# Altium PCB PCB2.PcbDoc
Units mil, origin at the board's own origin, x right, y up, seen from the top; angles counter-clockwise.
Board outline 1968.5 x 1968.5 mil, 4 copper layers (Top Layer, Internal Plane 1, Internal Plane 2, Bottom Layer), stack 18.2 mil thick; 11 components, 10 nets, 36 pads, 0 vias.
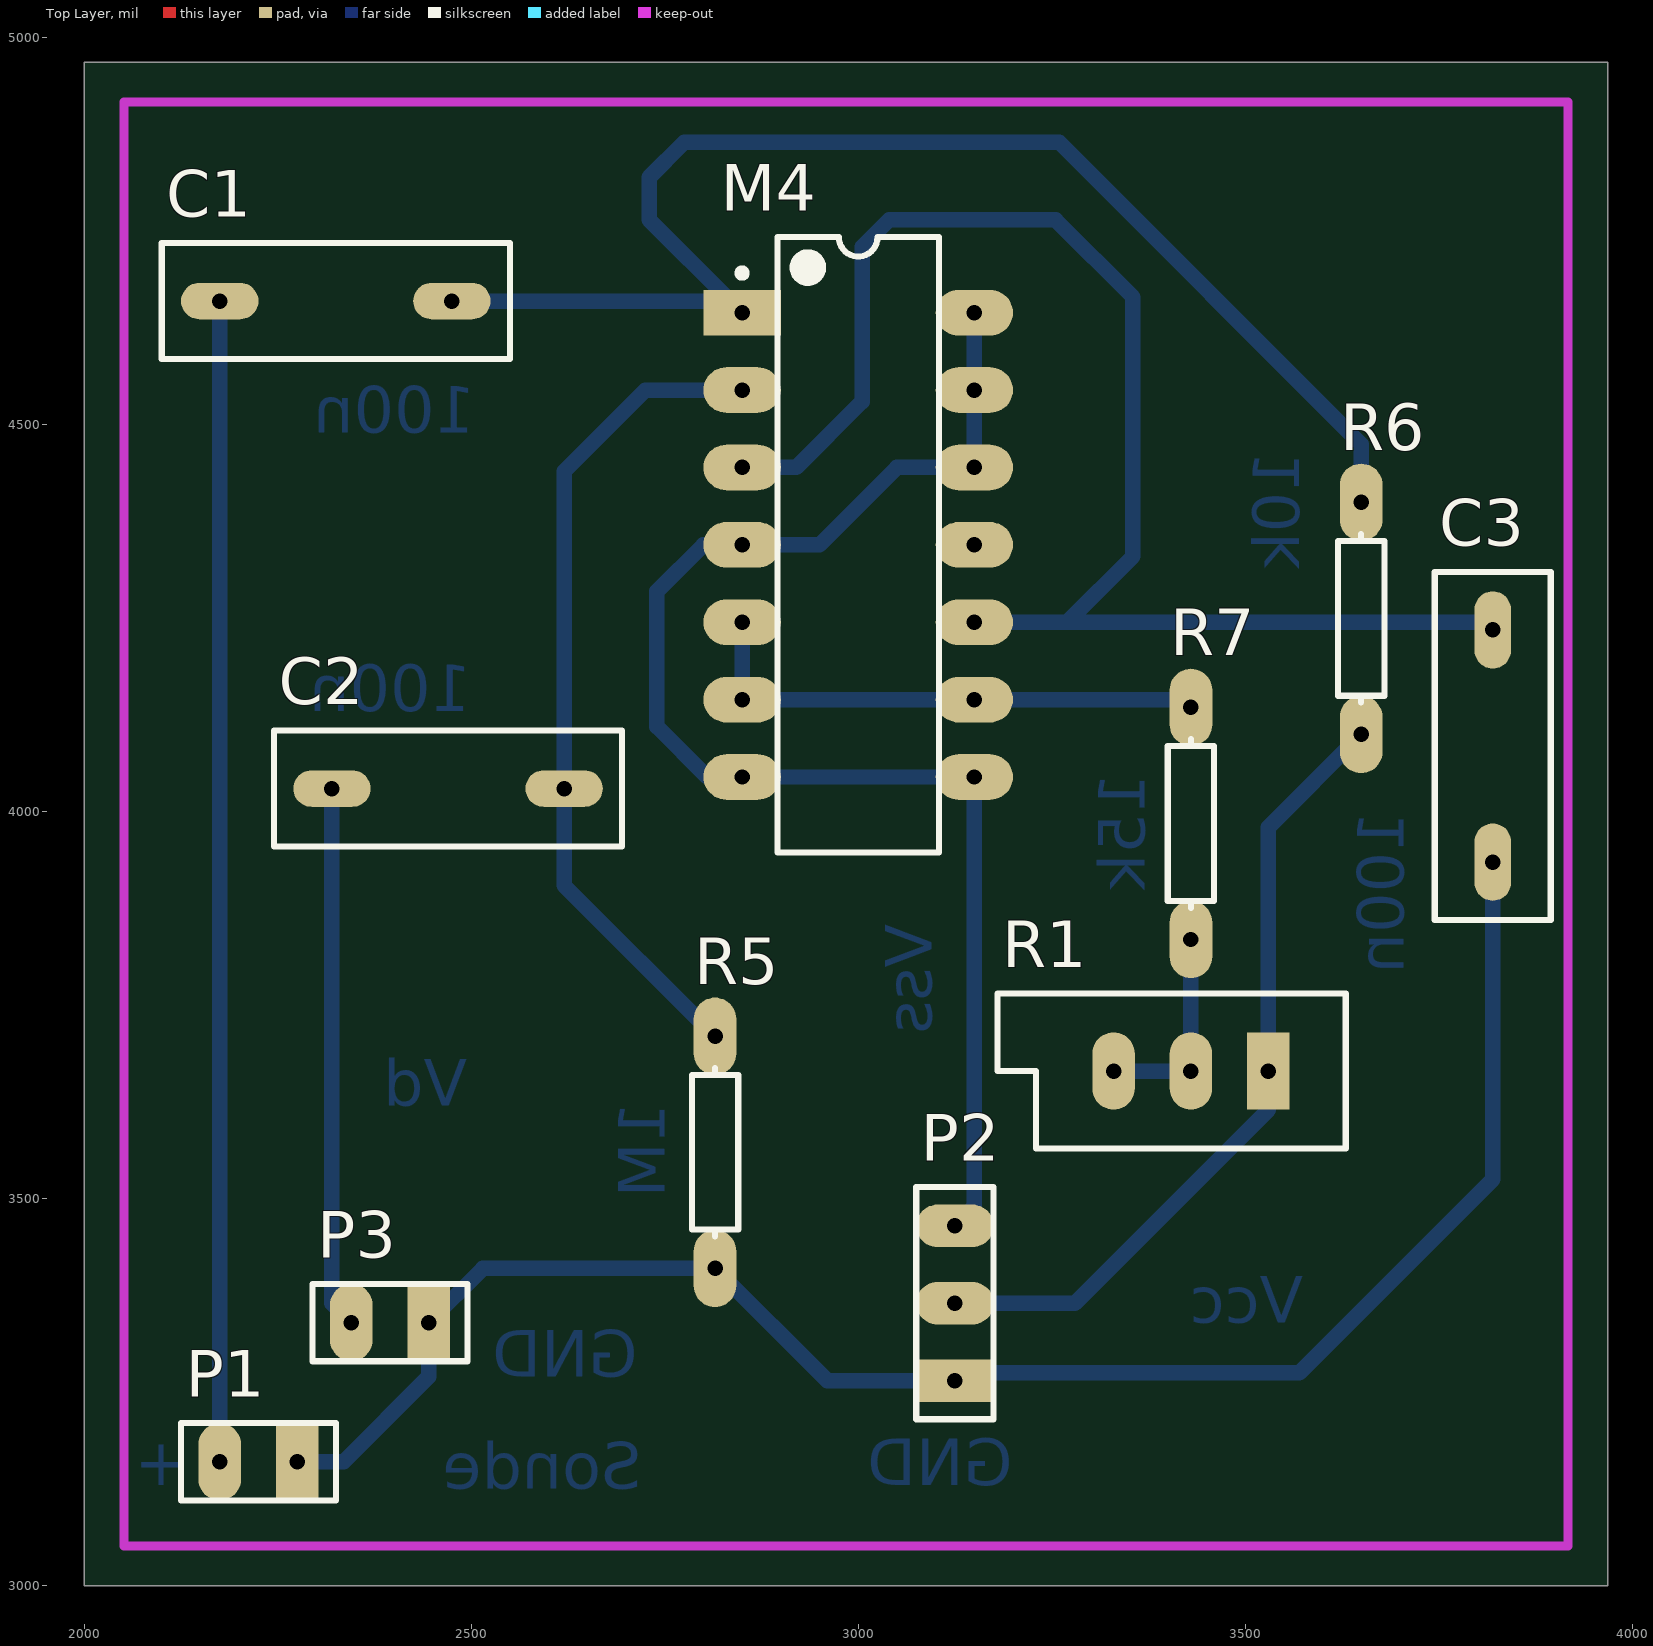
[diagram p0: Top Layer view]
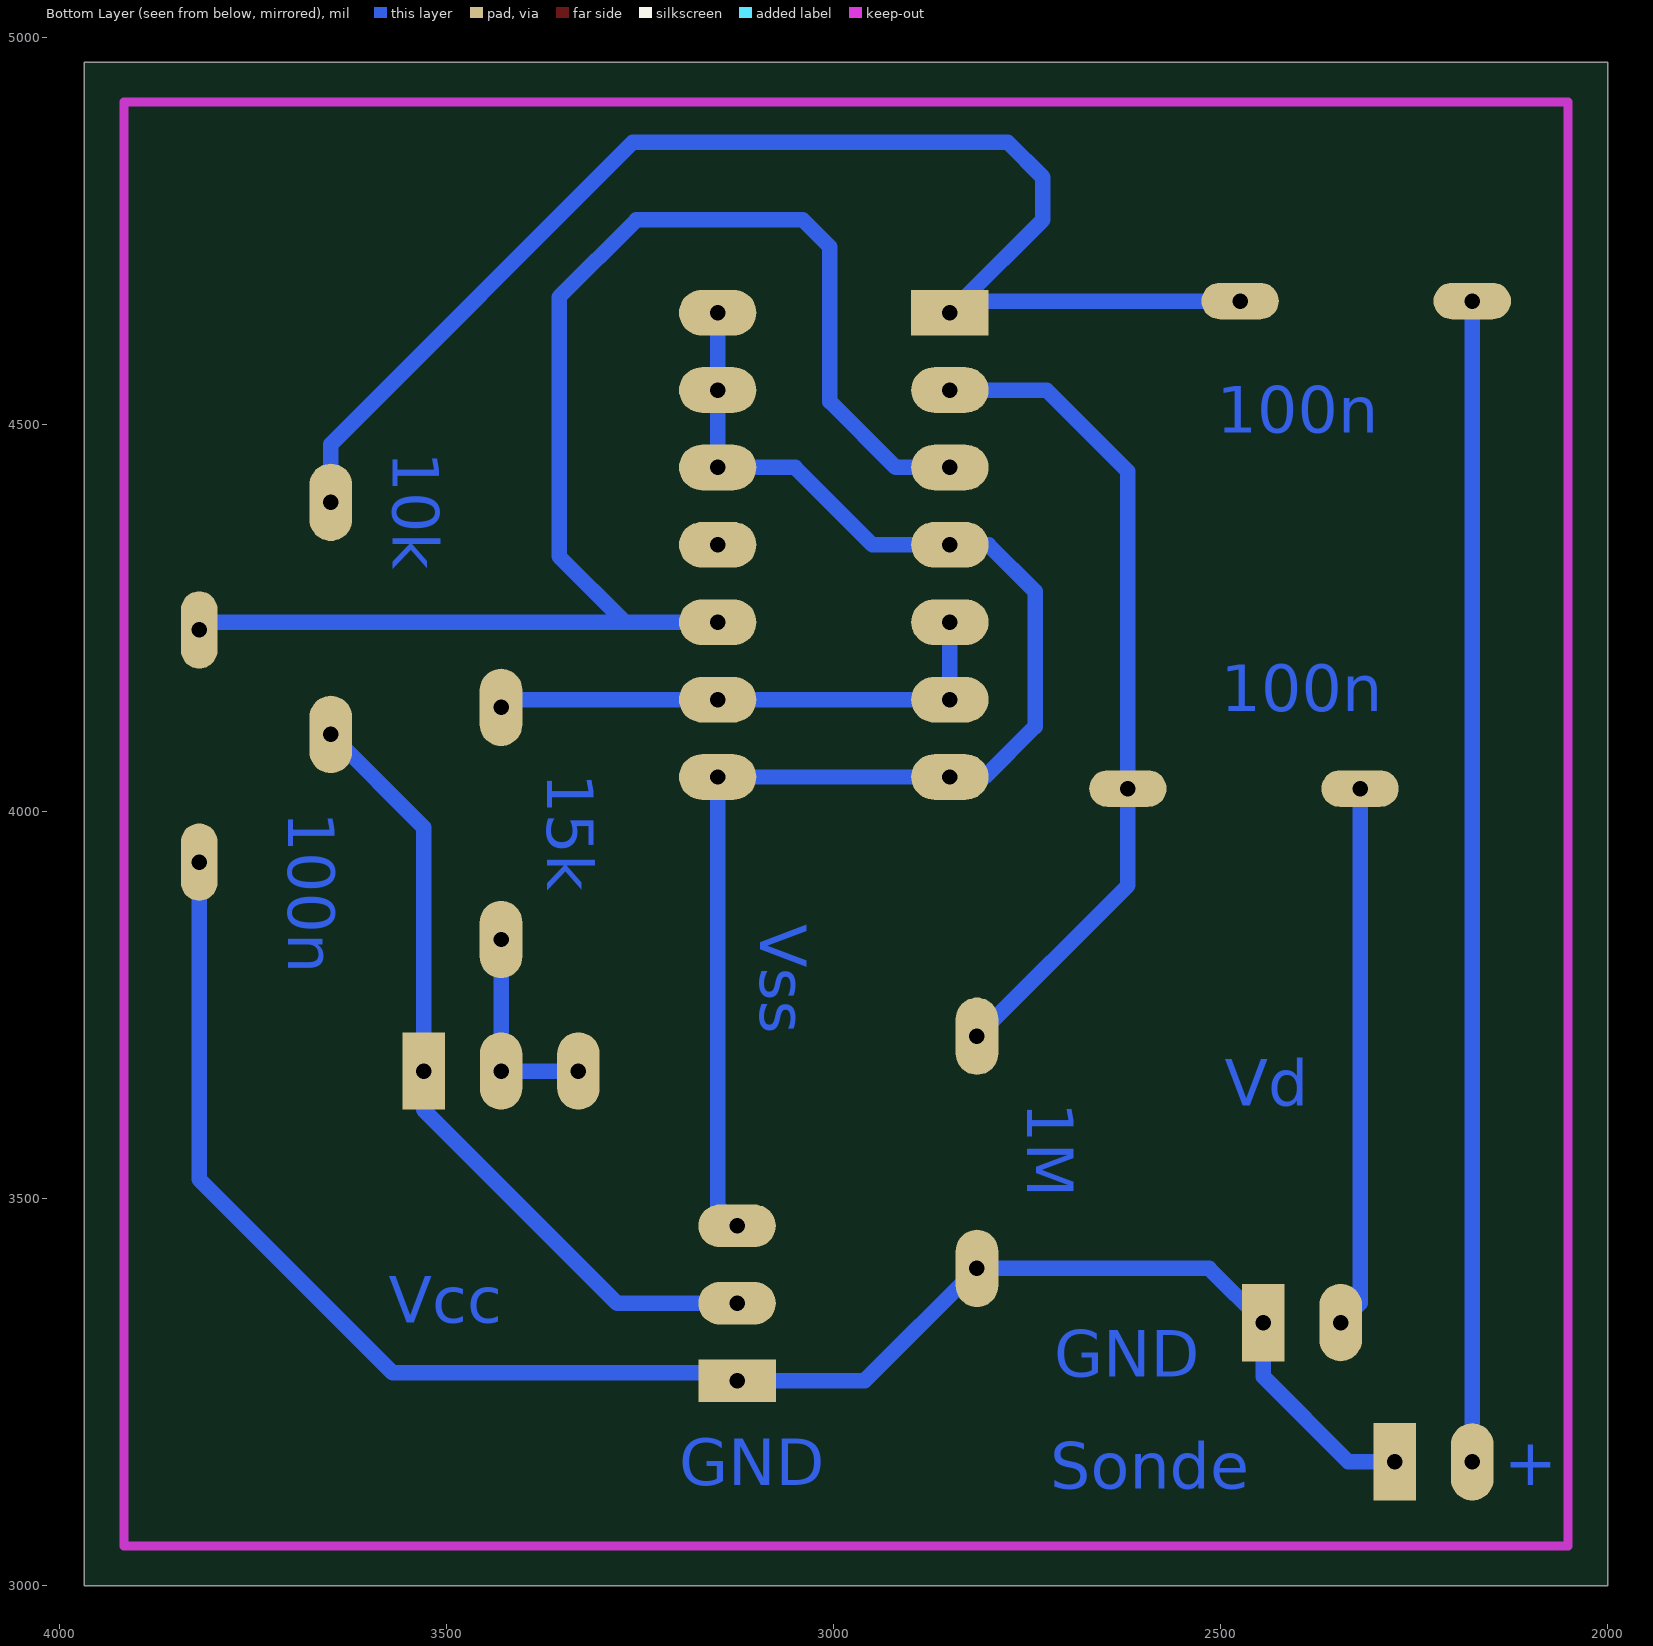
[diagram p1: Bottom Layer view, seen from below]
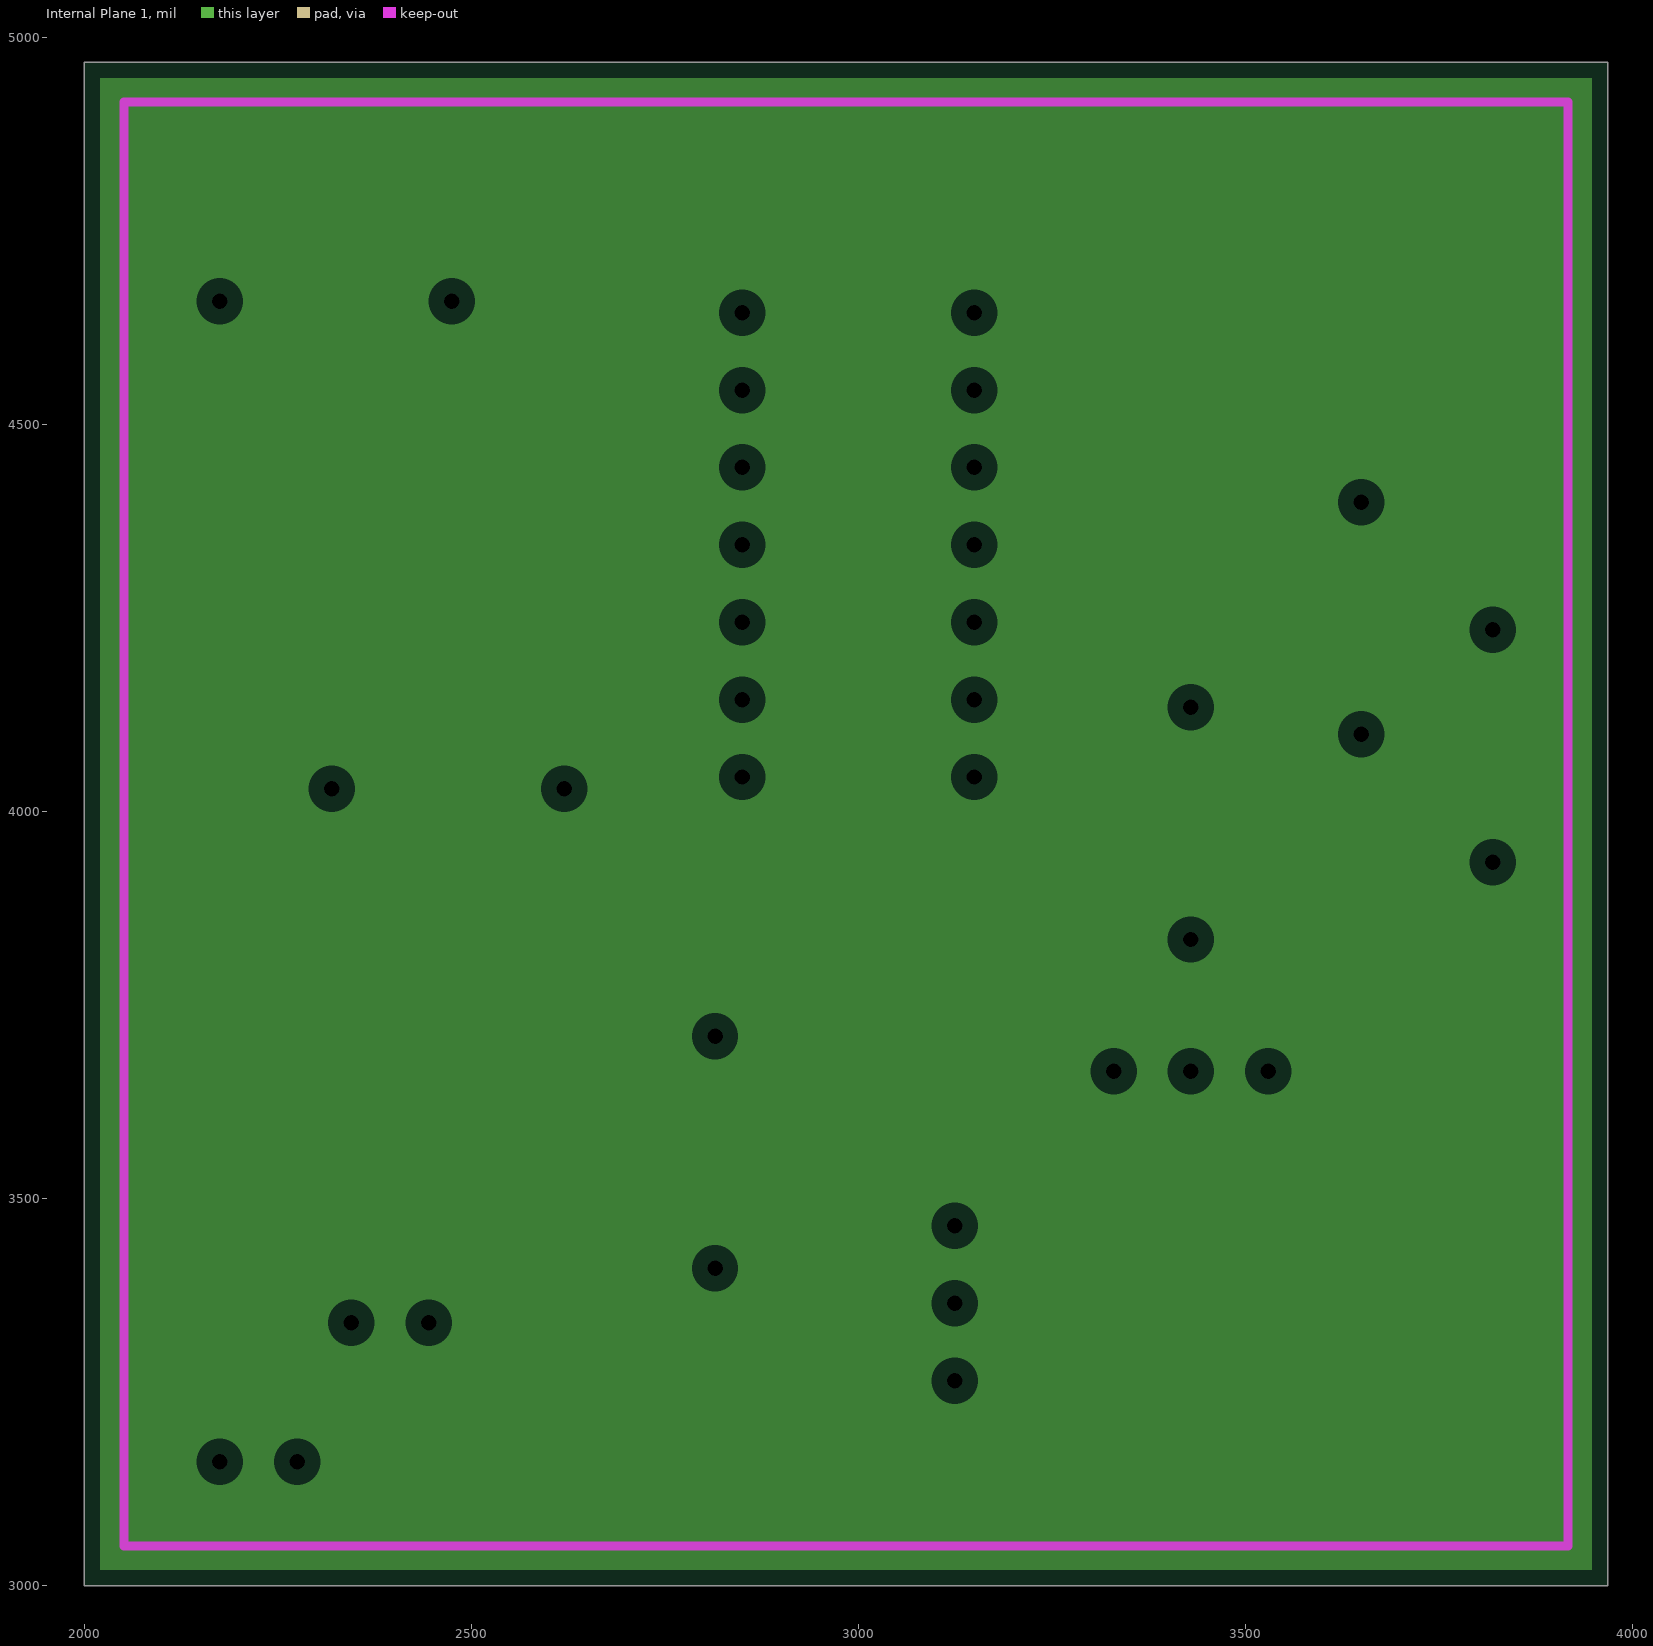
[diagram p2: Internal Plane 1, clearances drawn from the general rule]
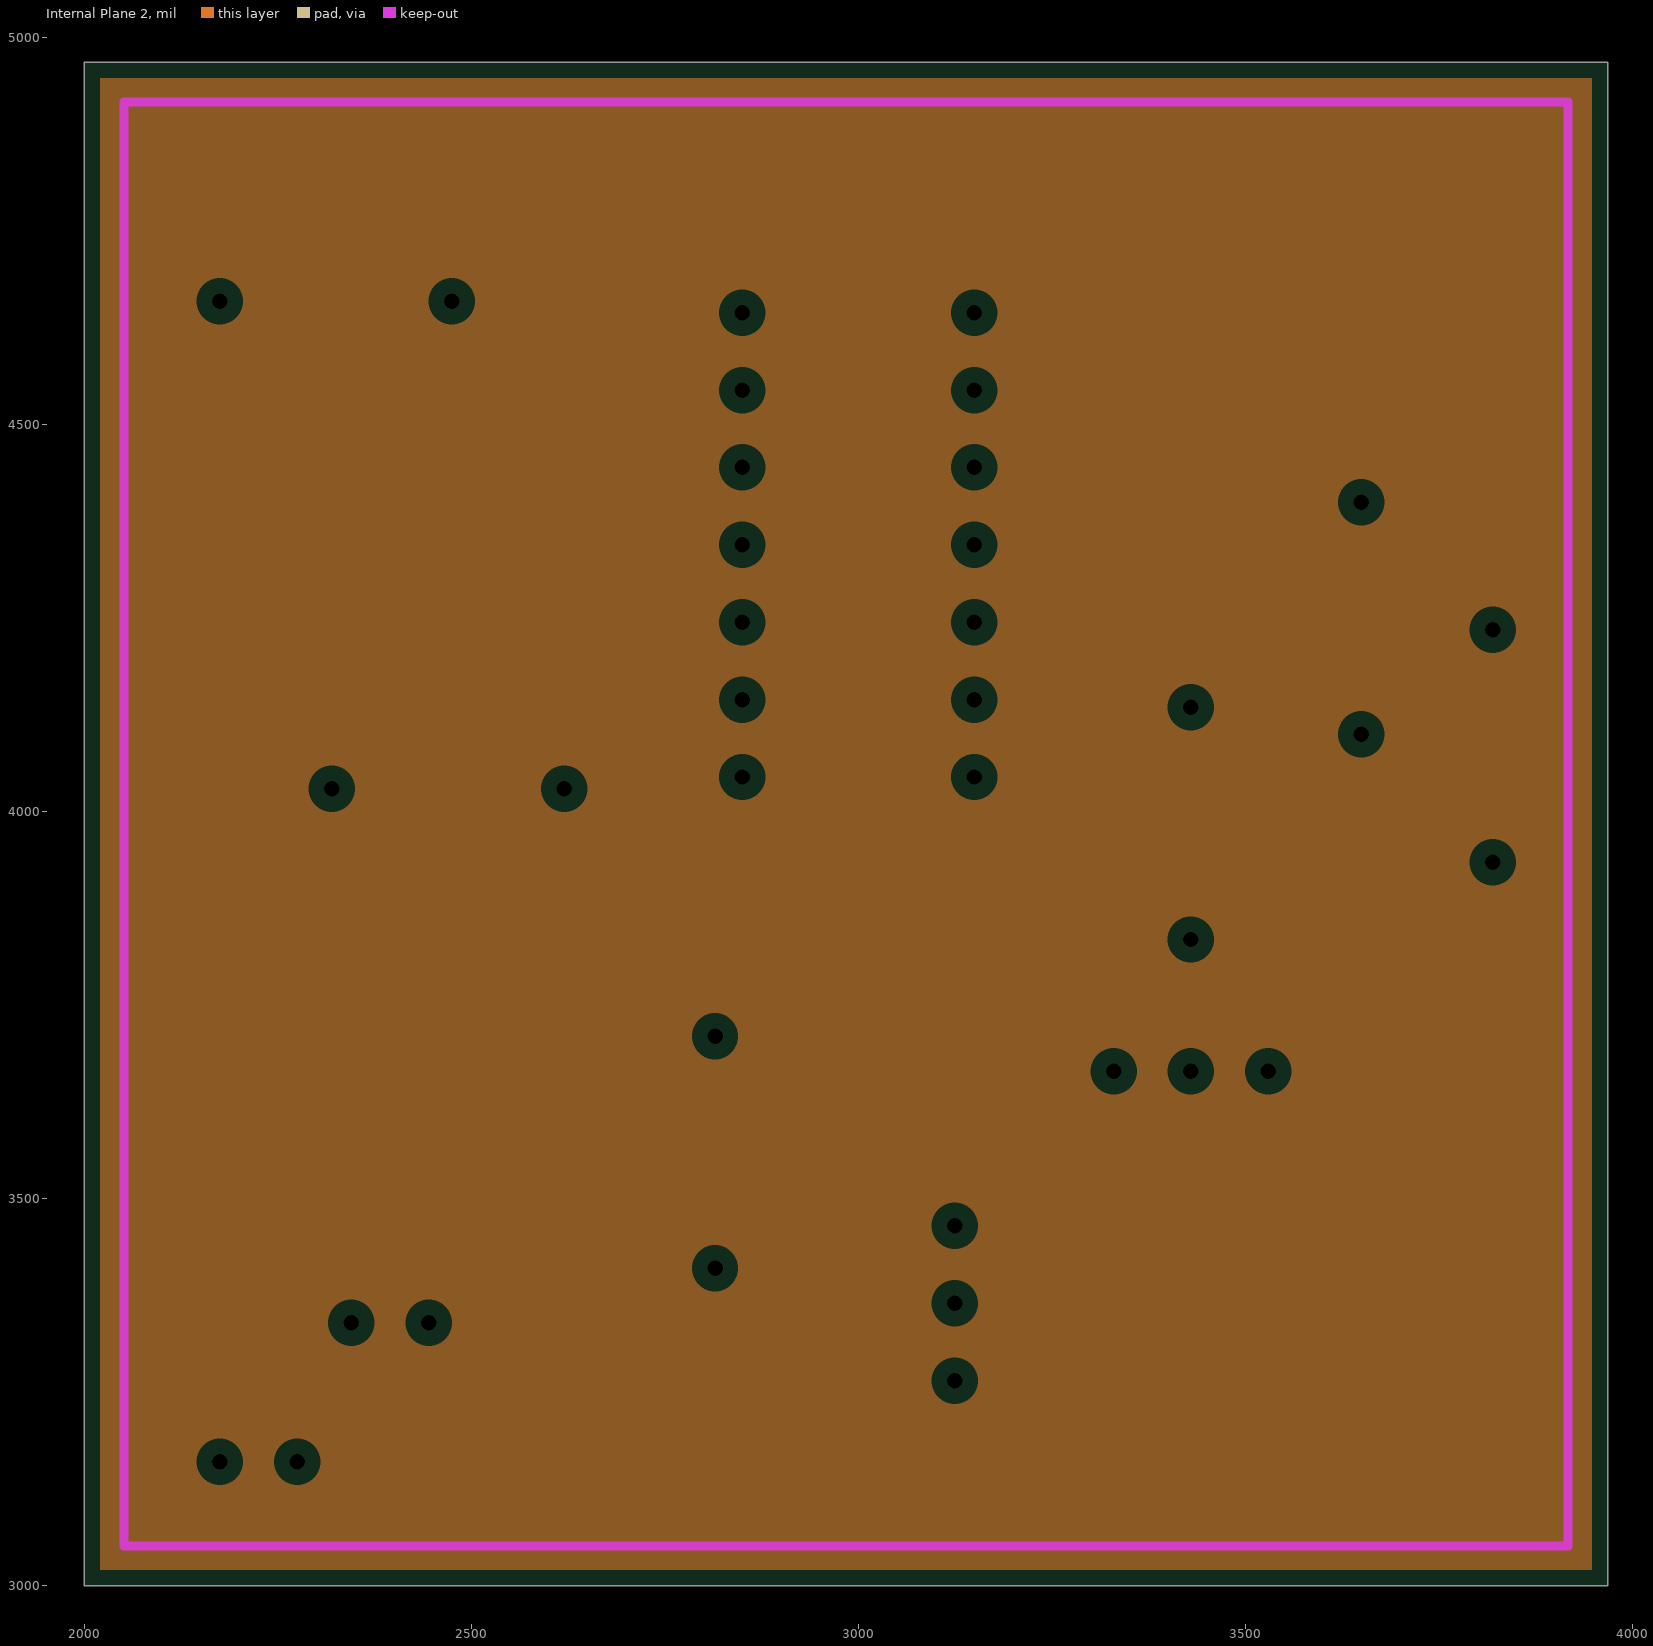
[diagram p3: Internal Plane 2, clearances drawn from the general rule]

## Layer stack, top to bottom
Top Solder: solder mask 0.4, Solder Resist, Dk 3.5
Top Layer: signal copper 1.4
Internal Plane 1: plane copper 1.4
Internal Plane 2: plane copper 1.4
Dielectric 1: dielectric 12.6, FR-4, Dk 4.8
Bottom Layer: signal copper 1.4
Bottom Solder: solder mask 0.4, Solder Resist, Dk 3.5

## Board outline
2000,3000 3968.5,3000 3968.5,4968.5 2000,4968.5

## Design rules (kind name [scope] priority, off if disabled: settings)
Clearance [All] p1: gap=30
PlaneClearance [All] p1: clearance=20
PlaneConnect [All] p1: planeconnectstyle=Relief reliefexpansion=20 reliefentries=4 reliefconductorwidth=10 reliefairgap=10
PolygonConnect [All] p1: connectstyle=Relief reliefconductorwidth=10 reliefentries=4 polygonreliefangle="90 Angle" airgapwidth=10
RoutingVias [All] p1: holewidth=32 width=62 viastyle="Through Hole" minholewidth=28 minwidth=50 maxholewidth=28 maxwidth=50
SolderMaskExpansion [All] p1: expansion=4
Width [All] p1: maxlimit=20 minlimit=20 preferedwidth=20
28 further rules are at their usual default settings.

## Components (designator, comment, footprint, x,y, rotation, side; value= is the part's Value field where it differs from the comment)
C1 "Cap" RAD-0.3 2325,4660 r180 top
C2 "Cap" RAD-0.3 2470,4030 r0 top
C3 "Cap" RAD-0.3 3820,4085 r270 top
M4 "ALD1106" DIP-14 3000,4345 r0 top
P1 "Header 2" HDR1X2 2275,3160 r180 top
P2 "Header 3" HDR1X3 3125,3265 r90 top
P3 "Header 2" HDR1X2 2445,3340 r180 top
R1 "RPot" VR5 3430,3665 r180 top
R5 "Res1" AXIAL-0.3 2815,3560 r90 top
R6 "Res1" AXIAL-0.3 3650,4250 r270 top
R7 "Res1" AXIAL-0.3 3430,3985 r270 top

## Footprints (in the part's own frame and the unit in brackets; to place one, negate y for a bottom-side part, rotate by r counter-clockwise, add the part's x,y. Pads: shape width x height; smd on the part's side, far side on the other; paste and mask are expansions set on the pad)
AXIAL-0.3 [mil] "Axial Device, Thru-Hole; 2 Leads; 0.3 in Pin Spacing"
  oval 100x55.12 hole 20: 1(-150,0) 2(150,0)
  silkscreen extent -109,-30 109,30
DIP-14 [mil] "DIP, 14-Pin, Row Spacing 7.62 mm, Pitch 2.54 mm"
  rect 100x59.06 hole 20: 1(-150,300)
  oval 100x59.06 hole 20: 2(-150,200) 3(-150,100) 4(-150,0) 5(-150,-100) 6(-150,-200) 7(-150,-300) 8(150,-300) 9(150,-200) 10(150,-100) 11(150,0) 12(150,100) 13(150,200) 14(150,300)
  silkscreen extent -155,-398 104,398, body extent -142,-398 142,398, height 200
HDR1X2 [mil] "Connector; Header; 2 Position"
  rect 55x100 hole 20: 1(0,0)
  oval 55x100 hole 20: 2(100,0)
  silkscreen extent -50,-50 150,50
HDR1X3 [mil] "Connector; Header; 3 Position"
  rect 55x100 hole 20: 1(0,0)
  oval 55x100 hole 20: 2(100,0) 3(200,0)
  silkscreen extent -50,-50 250,50
RAD-0.3 [mil] "Radial Cap, Thru-Hole; 2 Leads; 0.3 in Pin Spacing"
  oval 100x47.24 hole 20: 1(-150,0) 2(150,0)
  silkscreen extent -225,-75 225,75
VR5 [mil] "Thru-Hole; 3 Leads"
  rect 55x100 hole 20: 1(-100,0)
  oval 55x100 hole 20: 2(0,0) 3(100,0)
  silkscreen extent -200,-100 250,100

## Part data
C1 C2 C3: "Capacitor"
M4: "Quad N-channel matched MOSFET array"
P1 P3: "Header, 2-Pin"
P2: "Header, 3-Pin"
R1: "Potentiometer"
R5 R6 R7: "Resistor"

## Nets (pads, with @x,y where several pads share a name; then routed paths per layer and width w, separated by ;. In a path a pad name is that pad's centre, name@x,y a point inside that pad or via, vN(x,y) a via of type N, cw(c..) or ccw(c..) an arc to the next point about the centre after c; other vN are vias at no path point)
GND: C3.2 P1.1 P2.1 P3.1 R5.1 | length 2267.3
  Bottom Layer w20: P1.1 2335,3160 2445,3270 P3.1 2515,3410 R5.1 2960,3265 P2.1 3135,3275 3570,3275 3820,3525 C3.2
NetC1_1: C1.1 M4.1 R6.1 | length 1759.9
  Bottom Layer w20: C1.1 M4.1@2835,4660 ; M4.1 M4.1@2835,4660 ; R6.1 3650,4475 3260,4865 2775,4865 2730,4820 2730,4765 M4.1@2835,4660
NetC1_2: C1.2 P1.2 | length 1500
  Bottom Layer w20: P1.2 C1.2
NetC2_1: C2.1 P3.2 | length 700.4
  Bottom Layer w20: C2.1 2320,3365 P3.2
NetC2_2: C2.2 M4.2 R5.2 | length 1084.3
  Bottom Layer w20: R5.2 2620,3905 C2.2 2620,4440 2725,4545 M4.2
NetC3_1: C3.1 M4.3 M4.10 | length 2045.5
  Bottom Layer w20: M4.3 2920,4445 3005,4530 3005,4730 3040,4765 3255,4765 3355,4665 3355,4330 3270,4245 M4.10 3810,4245 C3.1
NetM4_4: M4.4 M4.7 M4.8 M4.12 M4.13 M4.14 P2.3 | length 1878.6
  Bottom Layer w20: P2.3 3150,3490 M4.8 M4.7 2805,4045 2740,4110 2740,4285 2800,4345 M4.4 2950,4345 3050,4445 M4.12 M4.13 M4.14
NetM4_5: M4.5 M4.6 M4.9 R7.1 | length 684.1
  Bottom Layer w20: M4.5 M4.6 M4.9 3420,4145 R7.1
NetR1_2: R1.2 R1.3 R7.2 | length 270
  Bottom Layer w20: R1.3 R1.2 R7.2
VCC: P2.2 R1.1 R6.2 | length 1043.3
  Bottom Layer w20: P2.2 3280,3365 3530,3615 R1.1 3530,3980 R6.2
pads on no net: M4.11

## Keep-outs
Keep-Out Layer:
  lines w11.81: 2051.18,3051.18 2051.18,4917.32 3917.32,4917.32 3917.32,3051.18 2051.18,3051.18

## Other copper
Bottom Layer:
  text "100n" at 2505,4490 h60
  text "10k" at 3570,4465 h60 r90
  text "100n" at 2500,4130 h60
  text "15k" at 3370,4050 h60 r90
  text "100n" at 3705,4000 h60 r90
  text "Vss" at 3095,3855 h60 r90
  text "1M" at 2750,3625 h60 r90
  text "Vd" at 2495,3620 h60
  text "Vcc" at 3575,3340 h60
  text "GND" at 2715,3270 h60
  text "+" at 2065,3130 h60
  text "GND" at 3200,3130 h60
  text "Sonde" at 2720,3125 h60

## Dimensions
2051.18,3051.18 to 2051.18,4917.32 on Mechanical 1
2051.18,3051.18 to 3917.32,3051.18 on Mechanical 1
